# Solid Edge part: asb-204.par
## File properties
Last saved by: nakano
Revision: 76
Density: 2552.91815623988 kg/m^3
Accuracy: 0.990
Material: Aluminium, 1350
Face Style: Aluminum
Fill Style: Normal
Virtual Style: Normal
Grouping: Other metals
LibraryName: Materials-GOST
Coef. of Thermal Exp: 2.3e-05
Thermal Conductivity: 233.0
Specific Heat: 920.0
Modulus of Elasticity: 68947570000.0
Poisson's Ratio: 0.33
Yield Stress: 27579028.0
Ultimate Stress: 82737084.0
Elongation: 0.0
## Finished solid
Body 1: solid body, 83 faces, 194 edges, 88 vertices.
  Faces by surface: cylinder 47, plane 36
  Edges by curve: line 100, circle 94
Bounding box of the edges (mm): 82.550 x 35.077 x 60.731, from (-41.275, 0, -36.9316) to (41.275, 35.0774, 23.7998).
Cylindrical faces by radius (mm): R0.254 x8, R0.8128 x3, R1.1938 x12, R1.5875 x2, R2.1844 x8, R2.3368 x3, R3.175 x8, R4.0005 x3
Planar faces by outward normal: +x 10, +y 4, +z 6, -x 10, -y 1, -z 5
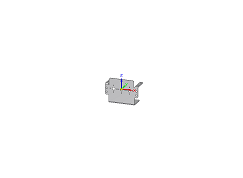
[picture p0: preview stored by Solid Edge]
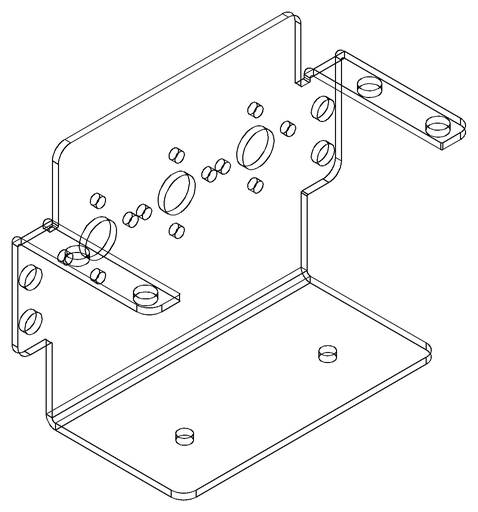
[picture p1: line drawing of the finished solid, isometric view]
